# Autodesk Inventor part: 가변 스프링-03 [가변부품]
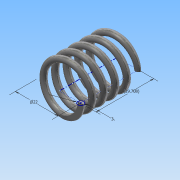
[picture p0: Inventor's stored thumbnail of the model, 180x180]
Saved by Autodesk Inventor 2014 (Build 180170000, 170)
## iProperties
Created: 2015-09
Part Number: 가변 스프링-03 [가변부품]
Material: 강철, 탄소
Document SubType Name: Modeling
Designer: study
Density: 7.87 g/cm^3
Appearance: 반연마
Mass: 18.806 g
Surface Area: 32.4603 cm^2
Volume: 2.38957 cm^3
Author: study
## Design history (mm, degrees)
sketch "스케치1"
  geometry: L1 (0, 0)-(11, 0); L2 (11, 0)-(11, 29.708); L3 (11, 29.708)-(0, 29.708); L4 (0, 29.708)-(0, 0); C1 r 1.5 at (11, 0)
  constraints: 8 end point, 2 parallel, 1 centre point, 1 coincident, 1 horizontal, 1 perpendicular
  dimensions: "d0" = 22 diameter of L2 L4; "d1" = 3 diameter of C1; "d2" = 29.70829 distance between parallel lines of L3 L1 (derived)
feature "코일1" sketch "스케치1" pitch "d3" = 10; turns "d5" = 5; dims "d4" = 29.70829 (= d2), "d6" = 0, angle "d7" = 90 deg, angle "d8" = 90 deg, "d9" = 0, "d10" = 0
node "작업 평면1"
sketch "스케치2"
  geometry: L1 (-12.5, 0)-(-9.5, 0) reference; 1 further point
  constraints: 1 horizontal alignment
extrude "돌출1" cut sketch "스케치2" stored distance "d12" = 10; taper "d13" = 0 deg
node "작업 평면2"
sketch "스케치3"
  geometry: L1 (-9.5, 0)-(-12.5, 0) reference; L2 (-9.5, 0)-(-12.5, 0) reference; 1 further point
  constraints: 2 horizontal alignment
extrude "돌출2" cut sketch "스케치3" stored distance "d15" = 10; taper "d16" = 0 deg
node "솔리드1"
node "절단 모서리 투영1"
node "절단 모서리 투영2"
node "절단 모서리 투영3"
other parameters: "d11" = 0, "d14" = 29.70829 (= d2)
